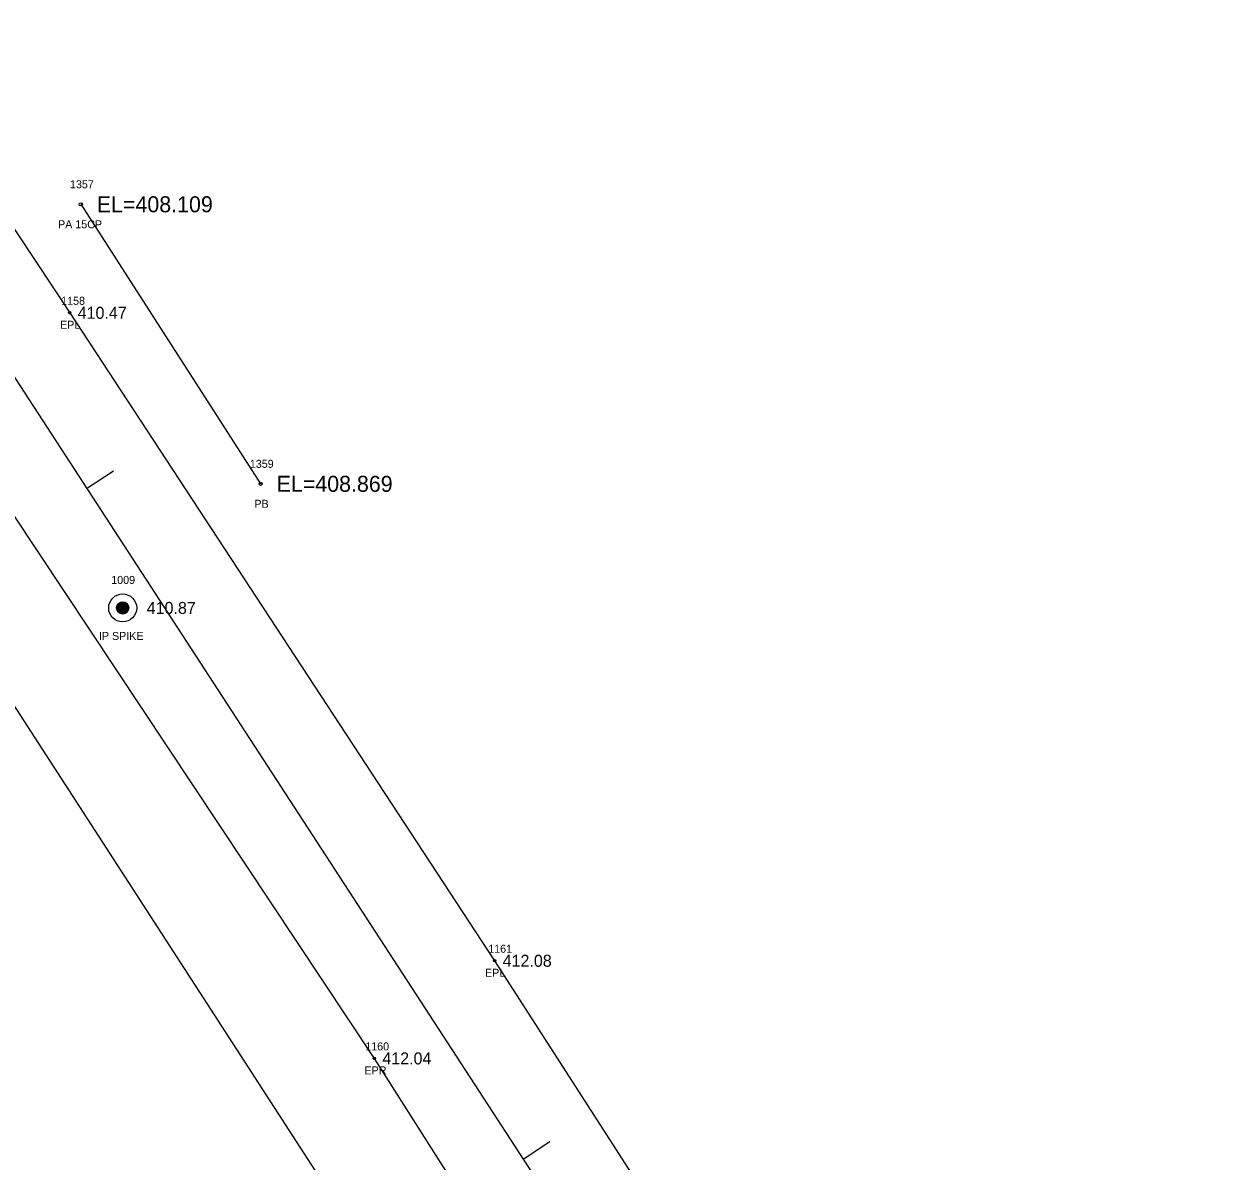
# Model space of a CAD drawing. Extents: x 2006517 to 2008868, y 1001613 to 1004633.
# Drawn here: x 2008653.5 to 2008801.8, y 1001785.7 to 1001927.8 of the extents above; entities that cross this region are included whole.
import ezdxf

# ---------------------------------------------------------------- set-up
doc = ezdxf.new("R2010")
doc.units = 0
for name, color, linetype in [('RD_EX_DR_Pipe', 7, 'Continuous'), ('RD_EX_DR_Pipe_txCode', 7, 'Continuous'), ('RD_EX_DV_Prop_txCode', 7, 'Continuous'), ('RD_EX_DV_PropPin', 7, 'Continuous'), ('RD_EX_Road', 7, 'Continuous'), ('RD_EX_Road_txCode', 7, 'Continuous'), ('RD_EX_TX_DV_Prop_ELEV', 7, 'Continuous'), ('RD_EX_TX_Road_ELEV', 7, 'Continuous'), ('RD_EX_VEG', 7, 'Continuous'), ('RD_HC_Cl', 7, 'Continuous'), ('RD_HC_Data_Tic', 7, 'Continuous'), ('RD_SMD_Locator', 7, 'Continuous'), ('RD_TX_Pipe_ElevEX', 7, 'Continuous')]:
    doc.layers.add(name, color=color, linetype=linetype)

msp = doc.modelspace()

# ---------------------------------------------------------------- linework, layer by layer
at = {"layer": 'RD_EX_DR_Pipe'}
msp.add_line((2008660.61, 1001905.25), (2008683.09, 1001870.32), dxfattribs=at)
at = {"layer": 'RD_EX_DV_PropPin'}
for p, q in [((2008665.11, 1001854.61), (2008665.11, 1001855)), ((2008665.15, 1001854.51), (2008665.15, 1001855.1)), ((2008665.18, 1001854.44), (2008665.18, 1001855.18)), ((2008665.22, 1001854.38), (2008665.22, 1001855.23)), ((2008665.25, 1001854.33), (2008665.25, 1001855.28)), ((2008665.29, 1001854.29), (2008665.29, 1001855.32)), ((2008665.32, 1001854.25), (2008665.32, 1001855.36)), ((2008665.36, 1001854.22), (2008665.36, 1001855.39)), ((2008665.39, 1001854.2), (2008665.39, 1001855.42)), ((2008665.43, 1001854.17), (2008665.43, 1001855.44)), ((2008665.46, 1001854.15), (2008665.46, 1001855.46)), ((2008665.5, 1001854.13), (2008665.5, 1001855.48)), ((2008665.53, 1001854.11), (2008665.53, 1001855.5)), ((2008665.57, 1001854.1), (2008665.57, 1001855.51)), ((2008665.6, 1001854.09), (2008665.6, 1001855.53)), ((2008665.64, 1001854.07), (2008665.64, 1001855.54)), ((2008665.67, 1001854.07), (2008665.67, 1001855.55)), ((2008665.71, 1001854.06), (2008665.71, 1001855.55)), ((2008665.74, 1001854.05), (2008665.74, 1001855.56)), ((2008665.78, 1001854.05), (2008665.78, 1001855.56)), ((2008665.81, 1001854.05), (2008665.81, 1001855.57)), ((2008665.85, 1001854.04), (2008665.85, 1001855.57)), ((2008665.88, 1001854.05), (2008665.88, 1001855.57)), ((2008665.92, 1001854.05), (2008665.92, 1001855.56)), ((2008665.95, 1001854.05), (2008665.95, 1001855.56)), ((2008665.99, 1001854.06), (2008665.99, 1001855.55)), ((2008666.02, 1001854.07), (2008666.02, 1001855.55)), ((2008666.06, 1001854.07), (2008666.06, 1001855.54)), ((2008666.09, 1001854.09), (2008666.09, 1001855.53)), ((2008666.13, 1001854.1), (2008666.13, 1001855.51)), ((2008666.17, 1001854.11), (2008666.17, 1001855.5)), ((2008666.2, 1001854.13), (2008666.2, 1001855.48)), ((2008666.24, 1001854.15), (2008666.24, 1001855.46)), ((2008666.27, 1001854.17), (2008666.27, 1001855.44)), ((2008666.31, 1001854.2), (2008666.31, 1001855.42)), ((2008666.34, 1001854.22), (2008666.34, 1001855.39)), ((2008666.38, 1001854.25), (2008666.38, 1001855.36)), ((2008666.41, 1001854.29), (2008666.41, 1001855.32)), ((2008666.45, 1001854.33), (2008666.45, 1001855.28)), ((2008666.48, 1001854.38), (2008666.48, 1001855.23)), ((2008666.52, 1001854.44), (2008666.52, 1001855.18)), ((2008666.55, 1001854.51), (2008666.55, 1001855.1)), ((2008666.59, 1001854.61), (2008666.59, 1001855))]:
    msp.add_line(p, q, dxfattribs=at)
for radius in [1.75, 0.761]:
    msp.add_circle((2008665.85, 1001854.81), radius, dxfattribs=at)
at = {"layer": 'RD_EX_Road'}
for points in [[(2007926.53, 1002880.46), (2007933.33, 1002888.64), (2008004.37, 1002823.78), (2008041.16, 1002791.39), (2008076.97, 1002755.85), (2008109.64, 1002720.02), (2008140.82, 1002682.03), (2008169.79, 1002642.37), (2008196.81, 1002603.48), (2008249.05, 1002522.64), (2008259.94, 1002505.27), (2008271.29, 1002488.2), (2008299.71, 1002443.6), (2008349.96, 1002366.27), (2008401.09, 1002286.99), (2008453.35, 1002207.39), (2008504.32, 1002128.41), (2008557.14, 1002047.24), (2008604.7, 1001974.22), (2008628.71, 1001937.76), (2008659.22, 1001891.69), (2008712.34, 1001810.72), (2008764.8, 1001729.24), (2008801.79, 1001664.14)], [(2008232, 1002511.78), (2008283.05, 1002433.59), (2008333.01, 1002355.46), (2008384.88, 1002276.31), (2008436.6, 1002196.52), (2008488.27, 1002116.95), (2008540.67, 1002036.8), (2008588.8, 1001963.64), (2008620.07, 1001915.65), (2008637.81, 1001888.3), (2008642.3, 1001881.28), (2008697.3, 1001798.52), (2008747.83, 1001719.05), (2008772.73, 1001677.09), (2008781, 1001661.78), (2008784.41, 1001655.25)]]:
    msp.add_lwpolyline(points, dxfattribs=at)
at = {"layer": 'RD_EX_VEG'}
msp.add_lwpolyline([(2007395.89, 1003327.12), (2007429.8, 1003285.17), (2007467.04, 1003247.92), (2007498.61, 1003210.85), (2007670.4, 1003045.37), (2007967.56, 1002793.96), (2008054.61, 1002736.66), (2008078.76, 1002693.39), (2008113.28, 1002661.09), (2008135.36, 1002619.06), (2008159.5, 1002583.06), (2008222.5, 1002503.36), (2008272.84, 1002426.91), (2008323.43, 1002347.7), (2008431.42, 1002192), (2008479.95, 1002108.23), (2008533.09, 1002033.28), (2008631.97, 1001873.89), (2008775.08, 1001653.06)], dxfattribs=at)
at = {"layer": 'RD_HC_Cl'}
msp.add_line((2008176.53, 1002614.55), (2008756.2, 1001724.02), dxfattribs=at)
at = {"layer": 'RD_HC_Data_Tic'}
for p, q in [((2008661.34, 1001869.75), (2008664.7, 1001871.93)), ((2008715.9, 1001785.94), (2008719.25, 1001788.12))]:
    msp.add_line(p, q, dxfattribs=at)
at = {"layer": 'RD_SMD_Locator'}
for centre, radius in [((2008660.61, 1001905.25), 0.2), ((2008659.22, 1001891.69), 0.15), ((2008683.09, 1001870.32), 0.2), ((2008665.85, 1001854.81), 0.15), ((2008712.34, 1001810.72), 0.15), ((2008697.3, 1001798.52), 0.15)]:
    msp.add_circle(centre, radius, dxfattribs=at)

# ---------------------------------------------------------------- texts
at = {"layer": 'RD_EX_DR_Pipe_txCode'}
for s, p in [('1357', (2008659.26, 1001907.25)), ('PA 15CP', (2008657.77, 1001902.25)), ('1359', (2008681.74, 1001872.32)), ('PB', (2008682.31, 1001867.32))]:
    msp.add_text(s, height=1, dxfattribs=at).set_placement(p)
at = {"layer": 'RD_EX_DV_Prop_txCode'}
for s, p in [('1009', (2008664.42, 1001857.81)), ('IP SPIKE', (2008662.88, 1001850.81))]:
    msp.add_text(s, height=1, dxfattribs=at).set_placement(p)
at = {"layer": 'RD_EX_Road_txCode'}
for s, p in [('1158', (2008658.16, 1001892.69)), ('EPL', (2008658.02, 1001889.69)), ('1161', (2008711.54, 1001811.72)), ('EPL', (2008711.14, 1001808.72)), ('1160', (2008696.17, 1001799.52)), ('EPR', (2008696.07, 1001796.52))]:
    msp.add_text(s, height=1, dxfattribs=at).set_placement(p)
at = {"layer": 'RD_EX_TX_DV_Prop_ELEV'}
msp.add_text('410.87', height=1.5, dxfattribs=at).set_placement((2008668.85, 1001854.06))
at = {"layer": 'RD_EX_TX_Road_ELEV'}
for s, p in [('410.47', (2008660.22, 1001890.94)), ('412.08', (2008713.34, 1001809.97)), ('412.04', (2008698.3, 1001797.77))]:
    msp.add_text(s, height=1.5, dxfattribs=at).set_placement(p)
at = {"layer": 'RD_TX_Pipe_ElevEX'}
for s, p in [('EL=408.109', (2008662.61, 1001904.25)), ('EL=408.869', (2008685.09, 1001869.32))]:
    msp.add_text(s, height=2, dxfattribs=at).set_placement(p)

doc.saveas('drawing.dxf')
